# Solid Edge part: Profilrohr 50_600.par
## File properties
Username: ahadarics
Dokumentum tartalom típus: 0
Author: ahadarics
Last saved by: ahadarics
Revision: 92
Sűrűség: 0,000 kg/m^3
Pontosság: 0,990
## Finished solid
Body 1: solid body, 175 faces, 519 edges, 346 vertices.
  Faces by surface: cylinder 107, plane 68
  Edges by curve: line 305, circle 214
Bounding box of the edges (mm): 60.200 x 60.200 x 644.000, from (-30.1, -30.1, -609.5) to (30.1, 30.1, 34.5).
Cylindrical faces by radius (mm): R0.1 x16, R0.2 x30, R0.5 x28, R1 x8, R3.75 x8, R5 x4, R6 x4, R25 x1, R27 x8
Planar faces by outward normal: +x 6, +y 6, +z 1, -x 4, -y 4, -z 1, oblique 46
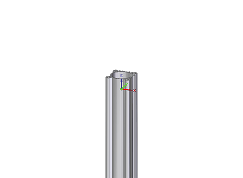
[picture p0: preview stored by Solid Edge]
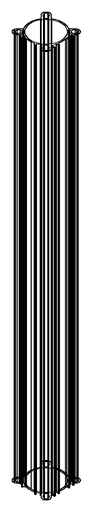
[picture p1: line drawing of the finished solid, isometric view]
